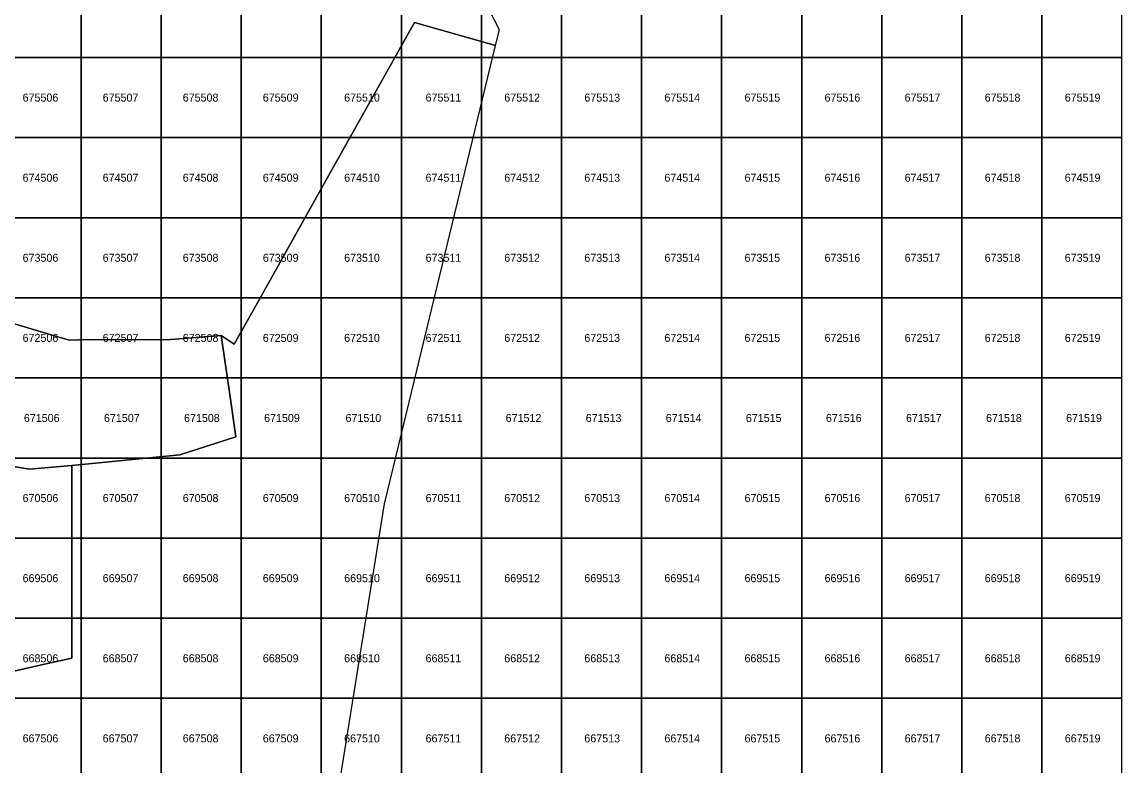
# Model space of a CAD drawing. Extents: x 25485000 to 25520000, y 6656775 to 6690000.
# Drawn here: x 25506262 to 25520000, y 6667155 to 6676444 of the extents above; entities that cross this region are included whole.
import ezdxf

# ---------------------------------------------------------------- set-up
doc = ezdxf.new("R2010")
doc.units = 0
doc.layers.add('Level 63', color=7, linetype='Continuous')

msp = doc.modelspace()

# ---------------------------------------------------------------- linework, layer by layer
at = {"layer": 'Level 63'}
for points in [[(25505896, 6672754), (25506849, 6672473), (25506981, 6672474), (25508116, 6672480), (25508747, 6672531), (25508913, 6672423), (25509223, 6672976), (25510000, 6674363), (25511162, 6676439), (25512177, 6676150), (25512224, 6676347), (25511165, 6678401)], [(25493980, 6658048), (25507391, 6664195), (25509799, 6663845), (25509837, 6664502), (25510789, 6670428), (25511000, 6671303), (25512177, 6676150), (25511162, 6676439), (25510000, 6674363), (25509223, 6672976), (25508913, 6672423), (25508747, 6672531), (25508848, 6671851), (25508934, 6671264), (25508231, 6671039), (25506885, 6670907), (25506884, 6670120), (25506882, 6668503), (25506580, 6668434), (25501638, 6667311)], [(25501638, 6667311), (25506580, 6668434), (25506882, 6668503), (25506884, 6670120), (25506885, 6670907), (25506355, 6670859), (25506104, 6670903)]]:
    msp.add_lwpolyline(points, dxfattribs=at)
for points in [[(25506000, 6676000), (25507000, 6676000), (25507000, 6677000), (25506000, 6677000)], [(25507000, 6676000), (25508000, 6676000), (25508000, 6677000), (25507000, 6677000)], [(25508000, 6676000), (25509000, 6676000), (25509000, 6677000), (25508000, 6677000)], [(25509000, 6676000), (25510000, 6676000), (25510000, 6677000), (25509000, 6677000)], [(25510000, 6676000), (25511000, 6676000), (25511000, 6677000), (25510000, 6677000)], [(25511000, 6676000), (25512000, 6676000), (25512000, 6677000), (25511000, 6677000)], [(25512000, 6676000), (25513000, 6676000), (25513000, 6677000), (25512000, 6677000)], [(25513000, 6676000), (25514000, 6676000), (25514000, 6677000), (25513000, 6677000)], [(25514000, 6676000), (25515000, 6676000), (25515000, 6677000), (25514000, 6677000)], [(25515000, 6676000), (25516000, 6676000), (25516000, 6677000), (25515000, 6677000)], [(25516000, 6676000), (25517000, 6676000), (25517000, 6677000), (25516000, 6677000)], [(25517000, 6676000), (25518000, 6676000), (25518000, 6677000), (25517000, 6677000)], [(25518000, 6676000), (25519000, 6676000), (25519000, 6677000), (25518000, 6677000)], [(25519000, 6676000), (25520000, 6676000), (25520000, 6677000), (25519000, 6677000)], [(25506000, 6675000), (25507000, 6675000), (25507000, 6676000), (25506000, 6676000)], [(25507000, 6675000), (25508000, 6675000), (25508000, 6676000), (25507000, 6676000)], [(25508000, 6675000), (25509000, 6675000), (25509000, 6676000), (25508000, 6676000)], [(25509000, 6675000), (25510000, 6675000), (25510000, 6676000), (25509000, 6676000)], [(25510000, 6675000), (25511000, 6675000), (25511000, 6676000), (25510000, 6676000)], [(25511000, 6675000), (25512000, 6675000), (25512000, 6676000), (25511000, 6676000)], [(25512000, 6675000), (25513000, 6675000), (25513000, 6676000), (25512000, 6676000)], [(25513000, 6675000), (25514000, 6675000), (25514000, 6676000), (25513000, 6676000)], [(25514000, 6675000), (25515000, 6675000), (25515000, 6676000), (25514000, 6676000)], [(25515000, 6675000), (25516000, 6675000), (25516000, 6676000), (25515000, 6676000)], [(25516000, 6675000), (25517000, 6675000), (25517000, 6676000), (25516000, 6676000)], [(25517000, 6675000), (25518000, 6675000), (25518000, 6676000), (25517000, 6676000)], [(25518000, 6675000), (25519000, 6675000), (25519000, 6676000), (25518000, 6676000)], [(25519000, 6675000), (25520000, 6675000), (25520000, 6676000), (25519000, 6676000)], [(25506000, 6674000), (25507000, 6674000), (25507000, 6675000), (25506000, 6675000)], [(25507000, 6674000), (25508000, 6674000), (25508000, 6675000), (25507000, 6675000)], [(25508000, 6674000), (25509000, 6674000), (25509000, 6675000), (25508000, 6675000)], [(25509000, 6674000), (25510000, 6674000), (25510000, 6675000), (25509000, 6675000)], [(25510000, 6674000), (25511000, 6674000), (25511000, 6675000), (25510000, 6675000)], [(25511000, 6674000), (25512000, 6674000), (25512000, 6675000), (25511000, 6675000)], [(25512000, 6674000), (25513000, 6674000), (25513000, 6675000), (25512000, 6675000)], [(25513000, 6674000), (25514000, 6674000), (25514000, 6675000), (25513000, 6675000)], [(25514000, 6674000), (25515000, 6674000), (25515000, 6675000), (25514000, 6675000)], [(25515000, 6674000), (25516000, 6674000), (25516000, 6675000), (25515000, 6675000)], [(25516000, 6674000), (25517000, 6674000), (25517000, 6675000), (25516000, 6675000)], [(25517000, 6674000), (25518000, 6674000), (25518000, 6675000), (25517000, 6675000)], [(25518000, 6674000), (25519000, 6674000), (25519000, 6675000), (25518000, 6675000)], [(25519000, 6674000), (25520000, 6674000), (25520000, 6675000), (25519000, 6675000)], [(25506000, 6673000), (25507000, 6673000), (25507000, 6674000), (25506000, 6674000)], [(25507000, 6673000), (25508000, 6673000), (25508000, 6674000), (25507000, 6674000)], [(25508000, 6673000), (25509000, 6673000), (25509000, 6674000), (25508000, 6674000)], [(25509000, 6673000), (25510000, 6673000), (25510000, 6674000), (25509000, 6674000)], [(25510000, 6673000), (25511000, 6673000), (25511000, 6674000), (25510000, 6674000)], [(25511000, 6673000), (25512000, 6673000), (25512000, 6674000), (25511000, 6674000)], [(25512000, 6673000), (25513000, 6673000), (25513000, 6674000), (25512000, 6674000)], [(25513000, 6673000), (25514000, 6673000), (25514000, 6674000), (25513000, 6674000)], [(25514000, 6673000), (25515000, 6673000), (25515000, 6674000), (25514000, 6674000)], [(25515000, 6673000), (25516000, 6673000), (25516000, 6674000), (25515000, 6674000)], [(25516000, 6673000), (25517000, 6673000), (25517000, 6674000), (25516000, 6674000)], [(25517000, 6673000), (25518000, 6673000), (25518000, 6674000), (25517000, 6674000)], [(25518000, 6673000), (25519000, 6673000), (25519000, 6674000), (25518000, 6674000)], [(25519000, 6673000), (25520000, 6673000), (25520000, 6674000), (25519000, 6674000)], [(25506000, 6672000), (25507000, 6672000), (25507000, 6673000), (25506000, 6673000)], [(25507000, 6672000), (25508000, 6672000), (25508000, 6673000), (25507000, 6673000)], [(25508000, 6672000), (25509000, 6672000), (25509000, 6673000), (25508000, 6673000)], [(25509000, 6672000), (25510000, 6672000), (25510000, 6673000), (25509000, 6673000)], [(25510000, 6672000), (25511000, 6672000), (25511000, 6673000), (25510000, 6673000)], [(25511000, 6672000), (25512000, 6672000), (25512000, 6673000), (25511000, 6673000)], [(25512000, 6672000), (25513000, 6672000), (25513000, 6673000), (25512000, 6673000)], [(25513000, 6672000), (25514000, 6672000), (25514000, 6673000), (25513000, 6673000)], [(25514000, 6672000), (25515000, 6672000), (25515000, 6673000), (25514000, 6673000)], [(25515000, 6672000), (25516000, 6672000), (25516000, 6673000), (25515000, 6673000)], [(25516000, 6672000), (25517000, 6672000), (25517000, 6673000), (25516000, 6673000)], [(25517000, 6672000), (25518000, 6672000), (25518000, 6673000), (25517000, 6673000)], [(25518000, 6672000), (25519000, 6672000), (25519000, 6673000), (25518000, 6673000)], [(25519000, 6672000), (25520000, 6672000), (25520000, 6673000), (25519000, 6673000)], [(25505098, 6671098), (25505454, 6671093), (25505832, 6670978), (25505947, 6670942), (25506104, 6670903), (25506355, 6670859), (25506885, 6670907), (25508231, 6671039), (25508934, 6671264), (25508848, 6671851), (25508747, 6672531), (25508116, 6672480), (25506981, 6672474), (25506849, 6672473), (25505896, 6672754), (25505431, 6671934), (25505368, 6671828), (25505338, 6671778), (25505099, 6671565)], [(25506000, 6671000), (25507000, 6671000), (25507000, 6672000), (25506000, 6672000)], [(25507000, 6671000), (25508000, 6671000), (25508000, 6672000), (25507000, 6672000)], [(25508000, 6671000), (25509000, 6671000), (25509000, 6672000), (25508000, 6672000)], [(25509000, 6671000), (25510000, 6671000), (25510000, 6672000), (25509000, 6672000)], [(25510000, 6671000), (25511000, 6671000), (25511000, 6672000), (25510000, 6672000)], [(25511000, 6671000), (25512000, 6671000), (25512000, 6672000), (25511000, 6672000)], [(25512000, 6671000), (25513000, 6671000), (25513000, 6672000), (25512000, 6672000)], [(25513000, 6671000), (25514000, 6671000), (25514000, 6672000), (25513000, 6672000)], [(25514000, 6671000), (25515000, 6671000), (25515000, 6672000), (25514000, 6672000)], [(25515000, 6671000), (25516000, 6671000), (25516000, 6672000), (25515000, 6672000)], [(25516000, 6671000), (25517000, 6671000), (25517000, 6672000), (25516000, 6672000)], [(25517000, 6671000), (25518000, 6671000), (25518000, 6672000), (25517000, 6672000)], [(25518000, 6671000), (25519000, 6671000), (25519000, 6672000), (25518000, 6672000)], [(25519000, 6671000), (25520000, 6671000), (25520000, 6672000), (25519000, 6672000)], [(25506000, 6670000), (25507000, 6670000), (25507000, 6671000), (25506000, 6671000)], [(25507000, 6670000), (25508000, 6670000), (25508000, 6671000), (25507000, 6671000)], [(25508000, 6670000), (25509000, 6670000), (25509000, 6671000), (25508000, 6671000)], [(25509000, 6670000), (25510000, 6670000), (25510000, 6671000), (25509000, 6671000)], [(25510000, 6670000), (25511000, 6670000), (25511000, 6671000), (25510000, 6671000)], [(25511000, 6670000), (25512000, 6670000), (25512000, 6671000), (25511000, 6671000)], [(25512000, 6670000), (25513000, 6670000), (25513000, 6671000), (25512000, 6671000)], [(25513000, 6670000), (25514000, 6670000), (25514000, 6671000), (25513000, 6671000)], [(25514000, 6670000), (25515000, 6670000), (25515000, 6671000), (25514000, 6671000)], [(25515000, 6670000), (25516000, 6670000), (25516000, 6671000), (25515000, 6671000)], [(25516000, 6670000), (25517000, 6670000), (25517000, 6671000), (25516000, 6671000)], [(25517000, 6670000), (25518000, 6670000), (25518000, 6671000), (25517000, 6671000)], [(25518000, 6670000), (25519000, 6670000), (25519000, 6671000), (25518000, 6671000)], [(25519000, 6670000), (25520000, 6670000), (25520000, 6671000), (25519000, 6671000)], [(25506000, 6669000), (25507000, 6669000), (25507000, 6670000), (25506000, 6670000)], [(25507000, 6669000), (25508000, 6669000), (25508000, 6670000), (25507000, 6670000)], [(25508000, 6669000), (25509000, 6669000), (25509000, 6670000), (25508000, 6670000)], [(25509000, 6669000), (25510000, 6669000), (25510000, 6670000), (25509000, 6670000)], [(25510000, 6669000), (25511000, 6669000), (25511000, 6670000), (25510000, 6670000)], [(25511000, 6669000), (25512000, 6669000), (25512000, 6670000), (25511000, 6670000)], [(25512000, 6669000), (25513000, 6669000), (25513000, 6670000), (25512000, 6670000)], [(25513000, 6669000), (25514000, 6669000), (25514000, 6670000), (25513000, 6670000)], [(25514000, 6669000), (25515000, 6669000), (25515000, 6670000), (25514000, 6670000)], [(25515000, 6669000), (25516000, 6669000), (25516000, 6670000), (25515000, 6670000)], [(25516000, 6669000), (25517000, 6669000), (25517000, 6670000), (25516000, 6670000)], [(25517000, 6669000), (25518000, 6669000), (25518000, 6670000), (25517000, 6670000)], [(25518000, 6669000), (25519000, 6669000), (25519000, 6670000), (25518000, 6670000)], [(25519000, 6669000), (25520000, 6669000), (25520000, 6670000), (25519000, 6670000)], [(25506000, 6668000), (25507000, 6668000), (25507000, 6669000), (25506000, 6669000)], [(25507000, 6668000), (25508000, 6668000), (25508000, 6669000), (25507000, 6669000)], [(25508000, 6668000), (25509000, 6668000), (25509000, 6669000), (25508000, 6669000)], [(25509000, 6668000), (25510000, 6668000), (25510000, 6669000), (25509000, 6669000)], [(25510000, 6668000), (25511000, 6668000), (25511000, 6669000), (25510000, 6669000)], [(25511000, 6668000), (25512000, 6668000), (25512000, 6669000), (25511000, 6669000)], [(25512000, 6668000), (25513000, 6668000), (25513000, 6669000), (25512000, 6669000)], [(25513000, 6668000), (25514000, 6668000), (25514000, 6669000), (25513000, 6669000)], [(25514000, 6668000), (25515000, 6668000), (25515000, 6669000), (25514000, 6669000)], [(25515000, 6668000), (25516000, 6668000), (25516000, 6669000), (25515000, 6669000)], [(25516000, 6668000), (25517000, 6668000), (25517000, 6669000), (25516000, 6669000)], [(25517000, 6668000), (25518000, 6668000), (25518000, 6669000), (25517000, 6669000)], [(25518000, 6668000), (25519000, 6668000), (25519000, 6669000), (25518000, 6669000)], [(25519000, 6668000), (25520000, 6668000), (25520000, 6669000), (25519000, 6669000)], [(25506000, 6667000), (25507000, 6667000), (25507000, 6668000), (25506000, 6668000)], [(25507000, 6667000), (25508000, 6667000), (25508000, 6668000), (25507000, 6668000)], [(25508000, 6667000), (25509000, 6667000), (25509000, 6668000), (25508000, 6668000)], [(25509000, 6667000), (25510000, 6667000), (25510000, 6668000), (25509000, 6668000)], [(25510000, 6667000), (25511000, 6667000), (25511000, 6668000), (25510000, 6668000)], [(25511000, 6667000), (25512000, 6667000), (25512000, 6668000), (25511000, 6668000)], [(25512000, 6667000), (25513000, 6667000), (25513000, 6668000), (25512000, 6668000)], [(25513000, 6667000), (25514000, 6667000), (25514000, 6668000), (25513000, 6668000)], [(25514000, 6667000), (25515000, 6667000), (25515000, 6668000), (25514000, 6668000)], [(25515000, 6667000), (25516000, 6667000), (25516000, 6668000), (25515000, 6668000)], [(25516000, 6667000), (25517000, 6667000), (25517000, 6668000), (25516000, 6668000)], [(25517000, 6667000), (25518000, 6667000), (25518000, 6668000), (25517000, 6668000)], [(25518000, 6667000), (25519000, 6667000), (25519000, 6668000), (25518000, 6668000)], [(25519000, 6667000), (25520000, 6667000), (25520000, 6668000), (25519000, 6668000)]]:
    msp.add_lwpolyline(points, close=True, dxfattribs=at)

# ---------------------------------------------------------------- texts
for s, p in [('675506', (25506269, 6675450)), ('675507', (25507269, 6675450)), ('675508', (25508269, 6675450)), ('675509', (25509269, 6675450)), ('675510', (25510285, 6675450)), ('675511', (25511302, 6675450)), ('675512', (25512285, 6675450)), ('675513', (25513285, 6675450)), ('675514', (25514285, 6675450)), ('675515', (25515285, 6675450)), ('675516', (25516285, 6675450)), ('675517', (25517285, 6675450)), ('675518', (25518285, 6675450)), ('675519', (25519285, 6675450)), ('674506', (25506269, 6674450)), ('674507', (25507269, 6674450)), ('674508', (25508269, 6674450)), ('674509', (25509269, 6674450)), ('674510', (25510285, 6674450)), ('674511', (25511302, 6674450)), ('674512', (25512285, 6674450)), ('674513', (25513285, 6674450)), ('674514', (25514285, 6674450)), ('674515', (25515285, 6674450)), ('674516', (25516285, 6674450)), ('674517', (25517285, 6674450)), ('674518', (25518285, 6674450)), ('674519', (25519285, 6674450)), ('673506', (25506269, 6673450)), ('673507', (25507269, 6673450)), ('673508', (25508269, 6673450)), ('673509', (25509269, 6673450)), ('673510', (25510285, 6673450)), ('673511', (25511302, 6673450)), ('673512', (25512285, 6673450)), ('673513', (25513285, 6673450)), ('673514', (25514285, 6673450)), ('673515', (25515285, 6673450)), ('673516', (25516285, 6673450)), ('673517', (25517285, 6673450)), ('673518', (25518285, 6673450)), ('673519', (25519285, 6673450)), ('672506', (25506269, 6672450)), ('672507', (25507269, 6672450)), ('672508', (25508269, 6672450)), ('672509', (25509269, 6672450)), ('672510', (25510285, 6672450)), ('672511', (25511302, 6672450)), ('672512', (25512285, 6672450)), ('672513', (25513285, 6672450)), ('672514', (25514285, 6672450)), ('672515', (25515285, 6672450)), ('672516', (25516285, 6672450)), ('672517', (25517285, 6672450)), ('672518', (25518285, 6672450)), ('672519', (25519285, 6672450)), ('671506', (25506285, 6671450)), ('671507', (25507285, 6671450)), ('671508', (25508285, 6671450)), ('671509', (25509285, 6671450)), ('671510', (25510302, 6671450)), ('671511', (25511318, 6671450)), ('671512', (25512302, 6671450)), ('671513', (25513302, 6671450)), ('671514', (25514302, 6671450)), ('671515', (25515302, 6671450)), ('671516', (25516302, 6671450)), ('671517', (25517302, 6671450)), ('671518', (25518302, 6671450)), ('671519', (25519302, 6671450)), ('670506', (25506269, 6670450)), ('670507', (25507269, 6670450)), ('670508', (25508269, 6670450)), ('670509', (25509269, 6670450)), ('670510', (25510285, 6670450)), ('670511', (25511302, 6670450)), ('670512', (25512285, 6670450)), ('670513', (25513285, 6670450)), ('670514', (25514285, 6670450)), ('670515', (25515285, 6670450)), ('670516', (25516285, 6670450)), ('670517', (25517285, 6670450)), ('670518', (25518285, 6670450)), ('670519', (25519285, 6670450)), ('669506', (25506269, 6669450)), ('669507', (25507269, 6669450)), ('669508', (25508269, 6669450)), ('669509', (25509269, 6669450)), ('669510', (25510285, 6669450)), ('669511', (25511302, 6669450)), ('669512', (25512285, 6669450)), ('669513', (25513285, 6669450)), ('669514', (25514285, 6669450)), ('669515', (25515285, 6669450)), ('669516', (25516285, 6669450)), ('669517', (25517285, 6669450)), ('669518', (25518285, 6669450)), ('669519', (25519285, 6669450)), ('668506', (25506269, 6668450)), ('668507', (25507269, 6668450)), ('668508', (25508269, 6668450)), ('668509', (25509269, 6668450)), ('668510', (25510285, 6668450)), ('668511', (25511302, 6668450)), ('668512', (25512285, 6668450)), ('668513', (25513285, 6668450)), ('668514', (25514285, 6668450)), ('668515', (25515285, 6668450)), ('668516', (25516285, 6668450)), ('668517', (25517285, 6668450)), ('668518', (25518285, 6668450)), ('668519', (25519285, 6668450)), ('667506', (25506269, 6667450)), ('667507', (25507269, 6667450)), ('667508', (25508269, 6667450)), ('667509', (25509269, 6667450)), ('667510', (25510285, 6667450)), ('667511', (25511302, 6667450)), ('667512', (25512285, 6667450)), ('667513', (25513285, 6667450)), ('667514', (25514285, 6667450)), ('667515', (25515285, 6667450)), ('667516', (25516285, 6667450)), ('667517', (25517285, 6667450)), ('667518', (25518285, 6667450)), ('667519', (25519285, 6667450))]:
    msp.add_text(s, height=100, dxfattribs=at).set_placement(p)

doc.saveas('drawing.dxf')
